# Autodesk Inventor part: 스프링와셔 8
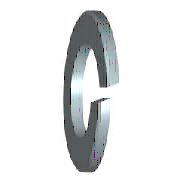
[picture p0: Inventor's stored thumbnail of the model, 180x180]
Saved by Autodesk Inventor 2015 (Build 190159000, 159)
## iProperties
IsCustomPart: 1
Created: 2012-02
Part Number: 스프링와셔 8
Material: 강철, 연강
Description: 스프링 잠금 와셔
Document SubType Name: Modeling
Standard: KS B 1324
Designer: mduedu
Standards Organization: KS
Language: ko-KR
Size Designation: 번호 3 - 8
Categories: <MemberInstance><Categories><Category DisplayName="조임쇠" InternalName="e4da775c-781d-43d5-af7c-5136215cf5a6" Mnemonic="FSTN"><Category DisplayName="와셔" InternalN
Density: 1 g/cm^3
Appearance: 파란색 - 벽 페인트 - 광택
Author: mduedu
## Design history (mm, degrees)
sketch "스케치1"
  geometry: C1 r 7.4 at (0, 0); C2 r 4.1 at (0, 0); 1 further point
  constraints: 2 centre point, 2 coincident
  dimensions: "d0" = 8.2 diameter of C2 (= SD1); "d1" = 14.8 diameter of C1 (= SD2)
extrude "본체" new body sketch "스케치1" distance "d2" = 2.5 (= SD); taper "d3" = 0 deg
sketch "스케치2"
  geometry: L1 (0, -4.1)-(0, 4.1) reference; L2 (2.5, 7.4)-(2.5, -7.4) reference; L3 (-1.2, 0)-(7.2, 0) reference; L4 (0, -0.5)-(2.5, 0.41); L5 (0, 0.5)-(2.5, 1.41)
  constraints: 4 end point, 4 point on line, 1 parallel
  dimensions: "d4" = 0.5 distance from line of L3 L4.start (= 0.2 x SD); "d5" = 0.5 distance from line of L3 L5.start (= 0.2 x SD); "d6" = 70 deg angle of L2 L4 (= FAWI)
extrude "절단부" cut sketch "스케치2" stored distance "d7" = 2.5 (= SD); taper "d8" = 0 deg
workaxis "Work Axis1"
workplane "Work Plane1"
body "Solid1"
other parameters: "SD1" = 8.2 [user parameter; used in 1 equation term], "SD2" = 14.8 [user parameter; used in 1 equation term], "SD" = 2.5 [user parameter; used in 4 equation terms], "FAWI" = 70 deg [user parameter; used in 1 equation term], "d9" = 0, "d10" = 0, "d11" = 0, "d12" = 0, "SDI" = 3.3 [user parameter], "NND" = 8 [user parameter]
